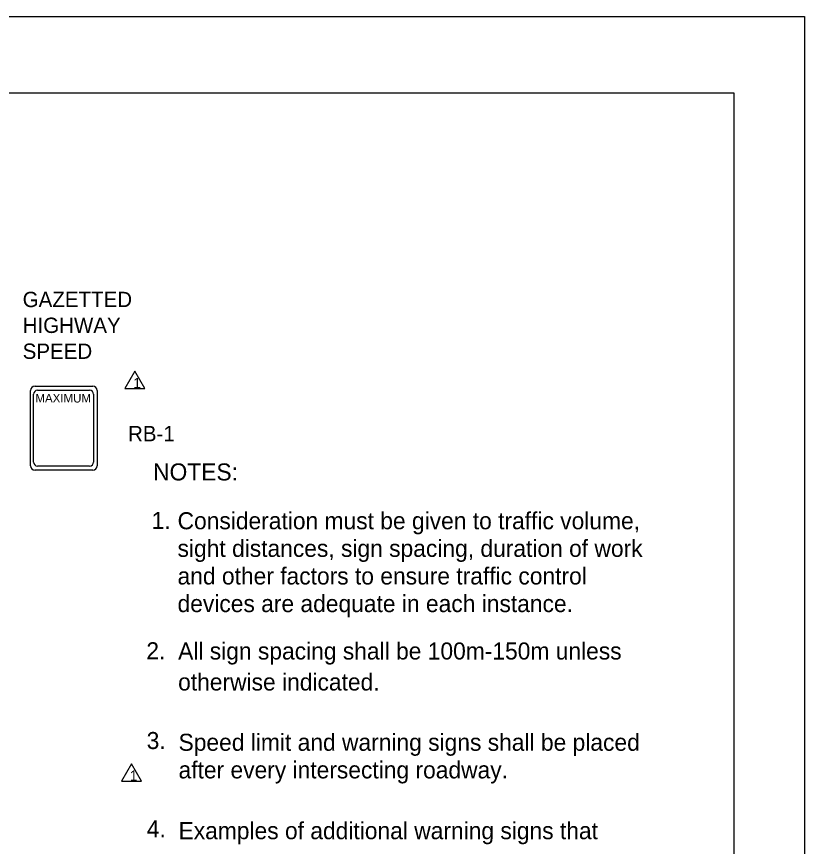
# Model space of a CAD drawing. Extents: x 2195 to 2411, y 202 to 481.
# Drawn here: x 2299.6 to 2411.4, y 363.1 to 480.9 of the extents above; entities that cross this region are included whole.
import ezdxf

# ---------------------------------------------------------------- set-up
doc = ezdxf.new("R2010")
doc.units = 0
for name, color, linetype in [('Level 1', 7, 'Continuous'), ('Level 10', 7, 'Continuous'), ('Level 44', 7, 'Continuous'), ('Level 60', 7, 'Continuous')]:
    doc.layers.add(name, color=color, linetype=linetype)

msp = doc.modelspace()

# ---------------------------------------------------------------- linework, layer by layer
at = {"layer": 'Level 1'}
for points in [[(2316.4, 430.54), (2314.98, 428.07), (2317.82, 428.07)], [(2315.91, 374.82), (2314.49, 372.35), (2317.33, 372.35)]]:
    msp.add_lwpolyline(points, close=True, dxfattribs=at)
at = {"layer": 'Level 44'}
for p, q in [((2301.59, 417.11), (2301.59, 427.79)), ((2302.22, 428.42), (2310.42, 428.42)), ((2302.58, 427.83), (2309.96, 427.83)), ((2311.05, 427.79), (2311.05, 417.11)), ((2302.01, 417.65), (2302.01, 427.26)), ((2310.53, 427.26), (2310.53, 417.65)), ((2301.59, 417.11), (2301.59, 417.11)), ((2302.01, 417.65), (2302.01, 417.65)), ((2309.96, 417.08), (2302.58, 417.08)), ((2310.42, 416.47), (2302.22, 416.47))]:
    msp.add_line(p, q, dxfattribs=at)
for centre, radius, start, end in [((2302.23, 427.79), 0.632, 90, 180), ((2302.58, 427.26), 0.569, 90, 180), ((2309.96, 427.26), 0.569, 360, 90), ((2310.42, 427.79), 0.632, 360, 90), ((2302.23, 417.11), 0.632, 180, 270), ((2302.58, 417.65), 0.569, 180, 270), ((2309.96, 417.65), 0.569, 270, 360), ((2310.42, 417.11), 0.632, 270, 360)]:
    msp.add_arc(centre, radius, start, end, dxfattribs=at)
at = {"layer": 'Level 60'}
for points in [[(2195.4, 480.88), (2411.4, 480.88), (2411.4, 201.88), (2195.4, 201.88)], [(2214.53, 470.07), (2401.4, 470.07), (2401.4, 212.69), (2214.53, 212.69)]]:
    msp.add_lwpolyline(points, close=True, dxfattribs=at)

# ---------------------------------------------------------------- texts
at = {"layer": 'Level 1'}
for p in [(2316.17, 428.13), (2315.68, 372.41)]:
    msp.add_text('1', height=1.45, rotation=360, dxfattribs=at).set_placement(p)
at = {"layer": 'Level 10'}
for s, p in [('GAZETTED ', (2300.47, 439.64)), ('HIGHWAY', (2300.47, 435.97)), ('SPEED', (2300.47, 432.29)), ('RB-1', (2315.42, 420.59))]:
    msp.add_text(s, height=2.177, rotation=360, dxfattribs=at).set_placement(p)
for s, p in [('NOTES:', (2318.98, 415.03)), ('1.', (2318.77, 408.15)), ('Consideration must be given to traffic volume,', (2322.45, 408.1)), ('sight distances, sign spacing, duration of work', (2322.45, 404.18)), ('and other factors to ensure traffic control ', (2322.45, 400.26)), ('devices are adequate in each instance.', (2322.45, 396.34)), ('2.', (2318.02, 389.64)), ('All sign spacing shall be 100m-150m unless', (2322.53, 389.61)), ('otherwise indicated.', (2322.53, 385.21)), ('3.', (2318.07, 376.9)), ('Speed limit and warning signs shall be placed', (2322.59, 376.65)), ('after every intersecting roadway.', (2322.59, 372.73)), ('4.', (2318.08, 364.36)), ('Examples of additional warning signs that ', (2322.59, 364.1))]:
    msp.add_text(s, height=2.419, dxfattribs=at).set_placement(p)
at = {"layer": 'Level 44'}
msp.add_text('MAXIMUM', height=1.221, dxfattribs=at).set_placement((2302.28, 426.1))

doc.saveas('drawing.dxf')
